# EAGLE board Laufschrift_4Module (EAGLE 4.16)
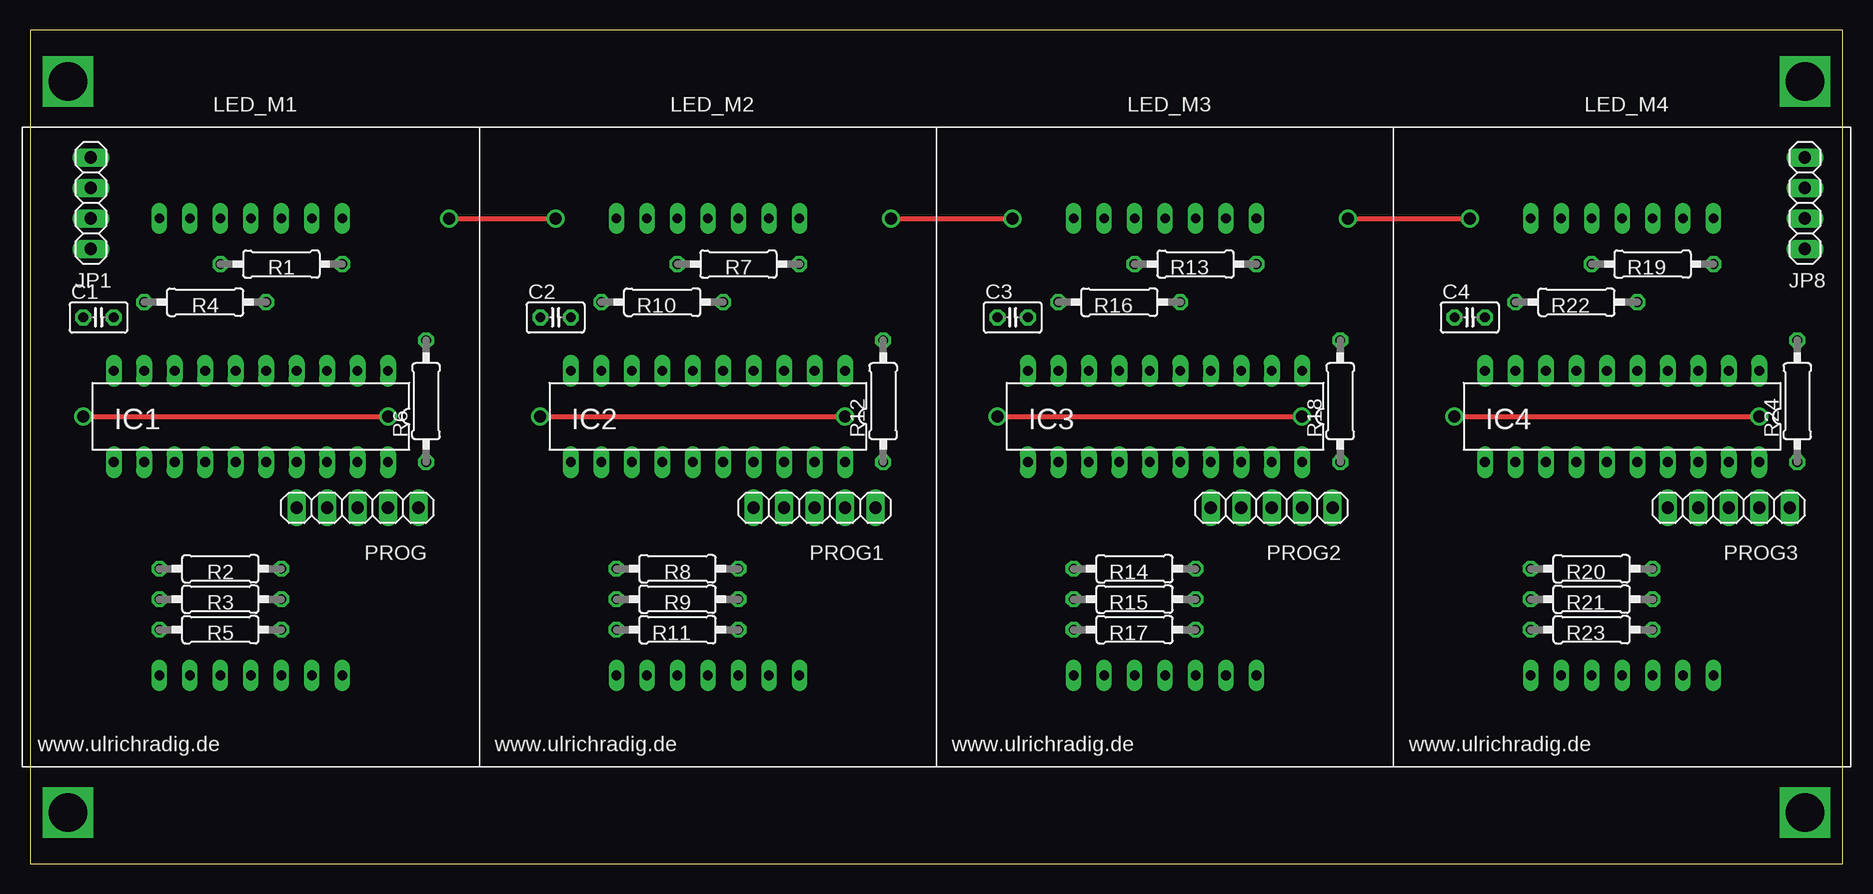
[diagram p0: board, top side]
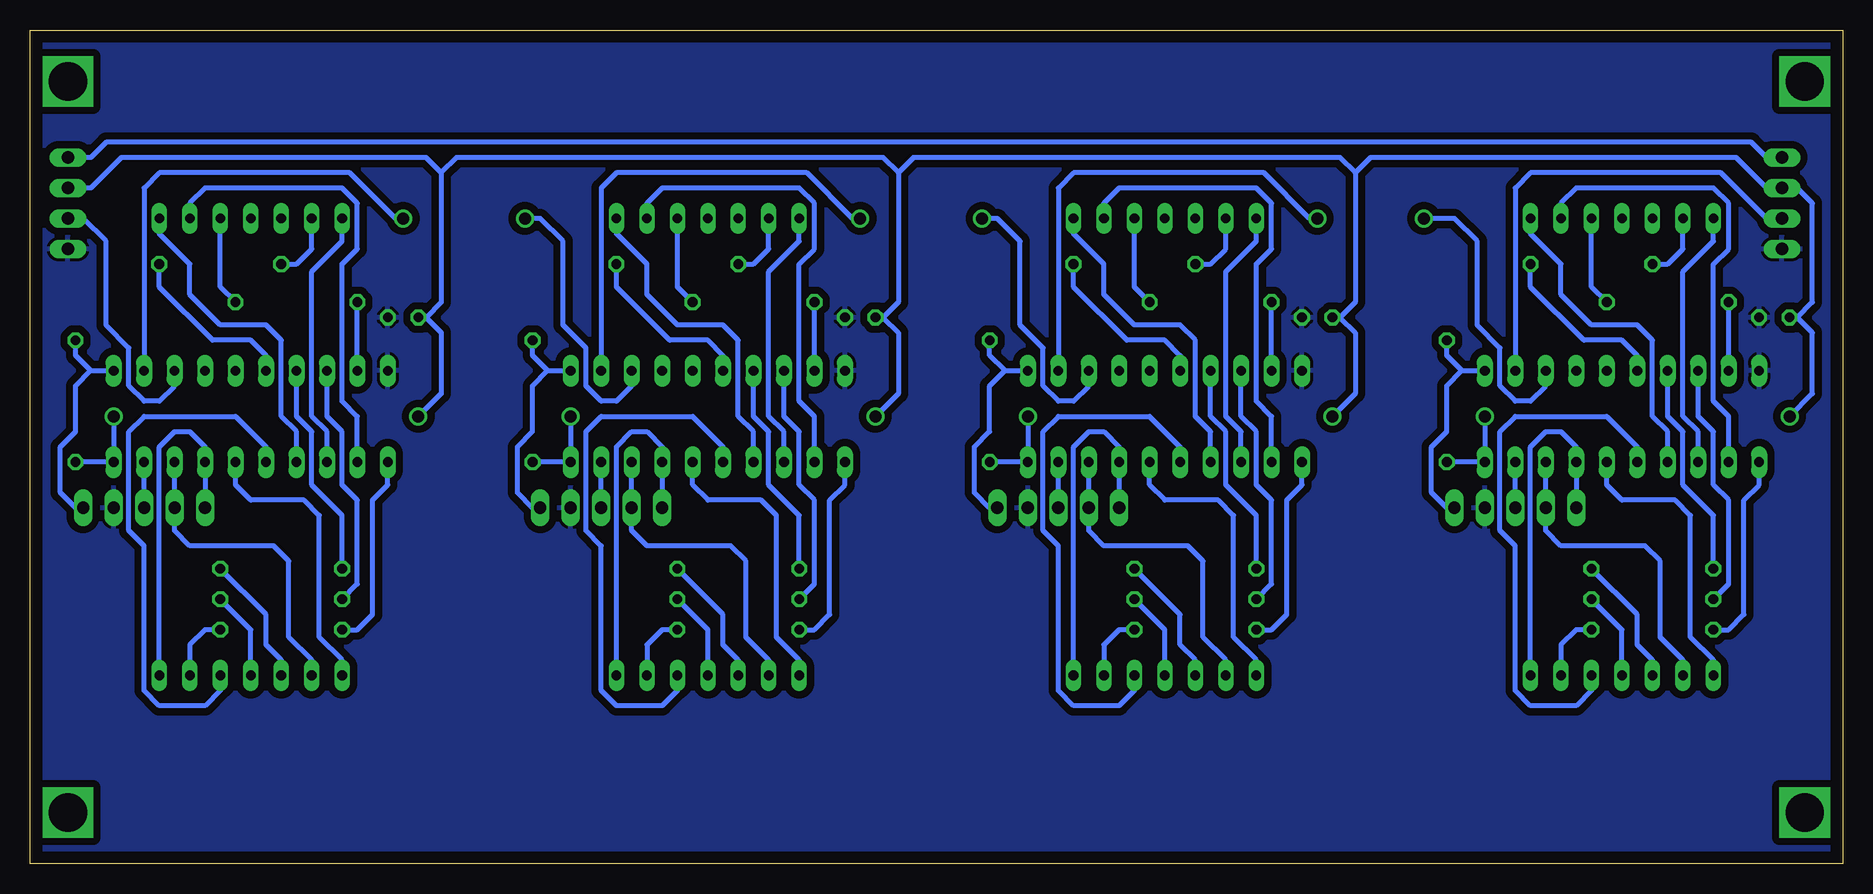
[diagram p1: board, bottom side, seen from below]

Size 151.11 x 69.52 mm. Coordinates in mm from the lower left corner, seen from the top.
Outline: 36.81,0 0,0 0,69.52 36.81,69.52
Outline: 36.83,0 151.11,0 151.11,69.52 36.83,69.52
Copper layers (1*16): Top 0.035mm / dielectric 1.5mm / Bottom 0.035mm
Design rules "default": minimum track width 10mil, minimum drill 24mil, track to track 8mil, track to pad 8mil, pad to pad 8mil, via to via 8mil, smd to smd 8mil, copper to edge 40mil, drill to drill 8mil, minimum pad ring 10mil, minimum via ring 8mil, stop-mask expansion 4mil, vias tented up to drill 0mil, thermal gap 10mil

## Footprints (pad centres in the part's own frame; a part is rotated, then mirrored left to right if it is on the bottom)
C025-025X050 = drill 0.813 octagon: 1 -1.27,0; 2 1.27,0
DIL20 = drill 0.813 long: 1 -11.43,-3.81; 2 -8.89,-3.81; 3 -6.35,-3.81; 4 -3.81,-3.81; 5 -1.27,-3.81; 6 1.27,-3.81; 7 3.81,-3.81; 8 6.35,-3.81; 9 8.89,-3.81; 10 11.43,-3.81; 11 11.43,3.81; 12 8.89,3.81; 13 6.35,3.81; 14 3.81,3.81; 15 1.27,3.81; 16 -1.27,3.81; 17 -3.81,3.81; 18 -6.35,3.81; 19 -8.89,3.81; 20 -11.43,3.81
1X04 = drill 1.016 long: 1 -3.81,0; 2 -1.27,0; 3 1.27,0; 4 3.81,0
LED_M = drill 0.8 long: 1 11.43,7.62; 2 13.97,7.62; 3 16.51,7.62; 4 19.05,7.62; 5 21.59,7.62; 6 24.13,7.62; 7 26.67,7.62; 8 26.67,45.72; 9 24.13,45.72; 10 21.59,45.72; 11 19.05,45.72; 12 16.51,45.72; 13 13.97,45.72; 14 11.43,45.72
1X05 = drill 1.016 long: 1 -5.08,0; 2 -2.54,0; 3 0,0; 4 2.54,0; 5 5.08,0
0207/10 = drill 0.813 octagon: 1 -5.08,0; 2 5.08,0

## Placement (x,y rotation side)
C1  [C025-025X050]  5.71,45.56 0 top
C2  [C025-025X050]  43.81,45.56 0 top
C3  [C025-025X050]  81.91,45.56 0 top
C4  [C025-025X050]  120.01,45.56 0 top
IC1  AT90S2313P  [DIL20]  18.41,37.3 180 top
IC2  AT90S2313P  [DIL20]  56.51,37.3 180 top
IC3  AT90S2313P  [DIL20]  94.61,37.3 180 top
IC4  AT90S2313P  [DIL20]  132.71,37.3 180 top
JP1  [1X04]  5.08,55.08 270 top
JP8  [1X04]  147.95,55.08 270 top
LED_M1  [LED_M]  -0.64,8.09 0 top
LED_M2  [LED_M]  37.46,8.09 0 top
LED_M3  [LED_M]  75.56,8.09 0 top
LED_M4  [LED_M]  113.66,8.09 0 top
PROG  [1X05]  27.3,29.68 180 top
PROG1  [1X05]  65.4,29.68 180 top
PROG2  [1X05]  103.5,29.68 180 top
PROG3  [1X05]  141.6,29.68 180 top
R1  [0207/10]  20.95,50 180 top
R2  [0207/10]  15.87,24.6 0 top
R3  [0207/10]  15.87,22.06 0 top
R4  [0207/10]  14.6,46.83 0 top
R5  [0207/10]  15.87,19.52 0 top
R6  [0207/10]  33.02,38.57 90 top
R7  [0207/10]  59.05,50 180 top
R8  [0207/10]  53.97,24.6 0 top
R9  [0207/10]  53.97,22.06 0 top
R10  [0207/10]  52.7,46.83 0 top
R11  [0207/10]  53.97,19.52 0 top
R12  [0207/10]  71.11,38.57 90 top
R13  [0207/10]  97.15,50 180 top
R14  [0207/10]  92.07,24.6 0 top
R15  [0207/10]  92.07,22.06 0 top
R16  [0207/10]  90.8,46.83 0 top
R17  [0207/10]  92.07,19.52 0 top
R18  [0207/10]  109.22,38.57 90 top
R19  [0207/10]  135.25,50 180 top
R20  [0207/10]  130.17,24.6 0 top
R21  [0207/10]  130.17,22.06 0 top
R22  [0207/10]  128.9,46.83 0 top
R23  [0207/10]  130.17,19.52 0 top
R24  [0207/10]  147.32,38.57 90 top

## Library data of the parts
C1-C4 R1-R24 = rcl
IC1-IC4 = atmel
JP1 JP8 PROG PROG1-PROG3 = pinhead
LED_M1-LED_M4 = led_matrix

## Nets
/RES: IC1.1 PROG.1 R6.2
/RES1: IC2.1 PROG1.1 R12.2
/RES2: IC3.1 PROG2.1 R18.2
/RES3: IC4.1 PROG3.1 R24.2
C1: LED_M1.13 R1.2
C2: LED_M1.3 R2.2
C3: LED_M1.4 R3.2
C4: LED_M1.10 R4.2
C5: LED_M1.6 R5.2
C6: LED_M2.6 R11.2
C7: LED_M2.10 R10.2
C8: LED_M2.4 R9.2
C9: LED_M2.3 R8.2
C10: LED_M2.13 R7.2
C11: LED_M3.6 R17.2
C12: LED_M3.10 R16.2
C13: LED_M3.4 R15.2
C14: LED_M3.3 R14.2
C15: LED_M3.13 R13.2
C16: LED_M4.6 R23.2
C17: LED_M4.10 R22.2
C18: LED_M4.4 R21.2
C19: LED_M4.3 R20.2
C20: LED_M4.13 R19.2
GND: C1.2 C2.2 C3.2 C4.2 IC1.10 IC2.10 IC3.10 IC4.10 JP1.4 JP8.4 PROG1.2 PROG2.2 PROG3.2 PROG.2
N$5: JP1.1 JP8.1
N$6: IC2.11 R11.1
N$7: IC2.9 R10.1
N$8: IC1.11 R5.1
N$9: IC1.9 R4.1
N$10: IC1.8 R3.1
N$11: IC1.7 R2.1
N$12: IC1.6 R1.1
N$13: IC2.8 R9.1
N$14: IC2.7 R8.1
N$15: IC2.6 R7.1
N$21: IC3.11 R17.1
N$22: IC3.9 R16.1
N$23: IC3.8 R15.1
N$24: IC3.7 R14.1
N$25: IC3.6 R13.1
N$31: IC4.11 R23.1
N$32: IC4.9 R22.1
N$33: IC4.8 R21.1
N$34: IC4.7 R20.1
N$35: IC4.6 R19.1
R1: IC1.12 LED_M1.9
R2: IC1.13 LED_M1.14
R3: IC1.14 LED_M1.8
R4: IC1.15 LED_M1.5
R5: IC1.16 LED_M1.1
R6: IC1.17 LED_M1.7 PROG.5
R7: IC1.18 LED_M1.2 PROG.4
R8: IC2.12 LED_M2.9
R9: IC2.13 LED_M2.14
R10: IC2.14 LED_M2.8
R11: IC2.15 LED_M2.5
R12: IC2.16 LED_M2.1
R13: IC2.17 LED_M2.7 PROG1.5
R14: IC2.18 LED_M2.2 PROG1.4
R15: IC3.12 LED_M3.9
R16: IC3.13 LED_M3.14
R17: IC3.14 LED_M3.8
R18: IC3.15 LED_M3.5
R19: IC3.16 LED_M3.1
R20: IC3.17 LED_M3.7 PROG2.5
R21: IC3.18 LED_M3.2 PROG2.4
R22: IC4.12 LED_M4.9
R23: IC4.13 LED_M4.14
R24: IC4.14 LED_M4.8
R25: IC4.15 LED_M4.5
R26: IC4.16 LED_M4.1
R27: IC4.17 LED_M4.7 PROG3.5
R28: IC4.18 LED_M4.2 PROG3.4
RXD: IC1.2 JP1.3
SCK: IC1.19 PROG.3
SCK1: IC2.19 PROG1.3
SCK2: IC3.19 PROG2.3
SCK3: IC4.19 PROG3.3
TXD: IC1.3 IC2.2
TXD1: IC2.3 IC3.2
TXD2: IC3.3 IC4.2
TXD3: IC4.3 JP8.3
VCC: C1.1 C2.1 C3.1 C4.1 IC1.20 IC2.20 IC3.20 IC4.20 JP1.2 JP8.2 R6.1 R12.1 R18.1 R24.1

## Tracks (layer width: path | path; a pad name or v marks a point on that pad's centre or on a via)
/RES
  Bottom 0.406: PROG.1 33.02,29.68 34.28,30.95 34.28,34.76 33.02,36.03 33.02,39.84 31.74,41.11 | 31.74,41.11 IC1.1 | R6.2 33.02,42.38 31.74,41.11
/RES1
  Bottom 0.406: PROG1.1 71.11,29.68 72.39,30.95 72.39,34.76 71.11,36.03 71.11,39.84 69.84,41.11 | 69.84,41.11 IC2.1 | R12.2 71.11,42.38 69.84,41.11
/RES2
  Bottom 0.406: PROG2.1 109.22,29.68 110.48,30.95 110.48,34.76 109.22,36.03 109.22,39.84 107.94,41.11 | 107.94,41.11 IC3.1 | R18.2 109.22,42.38 107.94,41.11
/RES3
  Bottom 0.406: PROG3.1 147.32,29.68 148.59,30.95 148.59,34.76 147.32,36.03 147.32,39.84 146.05,41.11 | 146.05,41.11 IC4.1 | R24.2 147.32,42.38 146.05,41.11
C1
  Bottom 0.406: R1.2 14.6,50 13.33,51.27 LED_M1.13
C2
  Bottom 0.406: LED_M1.3 15.87,16.98 17.14,18.25 17.14,20.79 R2.2
C3
  Bottom 0.406: LED_M1.4 18.41,19.52 R3.2
C4
  Bottom 0.406: R4.2 20.95,48.09 LED_M1.10
C5
  Bottom 0.406: R5.2 22.22,19.52 23.49,18.25 LED_M1.6
C6
  Bottom 0.406: R11.2 60.32,19.52 61.59,18.25 LED_M2.6
C7
  Bottom 0.406: R10.2 59.05,48.09 LED_M2.10
C8
  Bottom 0.406: LED_M2.4 56.51,19.52 R9.2
C9
  Bottom 0.406: LED_M2.3 53.97,16.98 55.24,18.25 55.24,20.79 R8.2
C10
  Bottom 0.406: R7.2 52.7,50 51.43,51.27 LED_M2.13
C11
  Bottom 0.406: R17.2 98.42,19.52 99.69,18.25 LED_M3.6
C12
  Bottom 0.406: R16.2 97.15,48.09 LED_M3.10
C13
  Bottom 0.406: LED_M3.4 94.61,19.52 R15.2
C14
  Bottom 0.406: LED_M3.3 92.07,16.98 93.34,18.25 93.34,20.79 R14.2
C15
  Bottom 0.406: R13.2 90.8,50 89.53,51.27 LED_M3.13
C16
  Bottom 0.406: R23.2 136.52,19.52 137.79,18.25 LED_M4.6
C17
  Bottom 0.406: R22.2 135.25,48.09 LED_M4.10
C18
  Bottom 0.406: LED_M4.4 132.71,19.52 R21.2
C19
  Bottom 0.406: LED_M4.3 130.17,16.98 131.44,18.25 131.44,20.79 R20.2
C20
  Bottom 0.406: R19.2 128.9,50 127.63,51.27 LED_M4.13
GND
  pour Bottom (isolate 0.61): -0.01,69.05 151.12,69.05 151.12,1.11 -0.01,1.11
N$1  (via drill 3.2)
  other vias: 3.17,65.24
N$3  (via drill 3.2)
  other vias: 3.17,4.28
N$5
  Bottom 0.406: JP1.1 6.35,58.89 7.62,60.16 144.78,60.16 146.05,58.89 JP8.1
N$6
  Bottom 0.406: R11.1 47.62,19.52 46.35,20.79 46.35,30.32 45.08,31.58 IC2.11
N$7
  Bottom 0.406: IC2.9 R10.1
N$8
  Bottom 0.406: R5.1 9.52,19.52 8.25,20.79 8.25,30.32 6.98,31.58 IC1.11
N$9
  Bottom 0.406: IC1.9 R4.1
N$10
  Bottom 0.406: R3.1 9.52,23.33 9.52,30.32 10.79,31.58 10.79,36.03 12.06,37.3 IC1.8
N$11
  Bottom 0.406: R2.1 10.79,29.04 13.33,31.58 13.33,36.03 14.6,37.3 IC1.7
N$12
  Bottom 0.406: IC1.6 17.14,42.38 18.41,43.65 21.59,43.65 26.03,48.09 R1.1
N$13
  Bottom 0.406: R9.1 47.62,23.33 47.62,30.32 48.89,31.58 48.89,36.03 50.16,37.3 IC2.8
N$14
  Bottom 0.406: R8.1 48.89,29.04 51.43,31.58 51.43,36.03 52.7,37.3 IC2.7
N$15
  Bottom 0.406: IC2.6 55.24,42.38 56.51,43.65 59.69,43.65 64.13,48.09 R7.1
N$21
  Bottom 0.406: R17.1 85.72,19.52 84.45,20.79 84.45,30.32 83.18,31.58 IC3.11
N$22
  Bottom 0.406: IC3.9 R16.1
N$23
  Bottom 0.406: R15.1 85.72,23.33 85.72,30.32 86.99,31.58 86.99,36.03 88.26,37.3 IC3.8
N$24
  Bottom 0.406: R14.1 86.99,29.04 89.53,31.58 89.53,36.03 90.8,37.3 IC3.7
N$25
  Bottom 0.406: IC3.6 93.34,42.38 94.61,43.65 97.78,43.65 102.23,48.09 R13.1
N$31
  Bottom 0.406: R23.1 123.82,19.52 122.55,20.79 122.55,30.32 121.28,31.58 IC4.11
N$32
  Bottom 0.406: IC4.9 R22.1
N$33
  Bottom 0.406: R21.1 123.82,23.33 123.82,30.32 125.09,31.58 125.09,36.03 126.36,37.3 IC4.8
N$34
  Bottom 0.406: R20.1 125.09,29.04 127.63,31.58 127.63,36.03 128.9,37.3 IC4.7
N$35
  Bottom 0.406: IC4.6 131.44,42.38 132.71,43.65 135.89,43.65 140.33,48.09 R19.1
N$37  (via drill 3.2)
  other vias: 147.95,65.24
N$39  (via drill 3.2)
  other vias: 147.95,4.28
R1
  Bottom 0.406: IC1.12 9.52,37.3 10.79,38.57 10.79,50 9.52,51.27 9.52,55.08 10.79,56.35 22.22,56.35 23.49,55.08 LED_M1.9
R2
  Bottom 0.406: IC1.13 12.06,36.03 13.33,37.3 13.33,49.37 10.79,51.91 LED_M1.14
R3
  Bottom 0.406: IC1.14 14.6,36.03 15.87,37.3 15.87,43.65 17.14,44.92 20.95,44.92 23.49,47.46 23.49,50 26.03,52.54 LED_M1.8
R4
  Bottom 0.406: IC1.15 17.14,34.76 19.68,37.3 27.3,37.3 28.57,36.03 28.57,27.78 27.3,26.5 27.3,14.44 26.03,13.17 22.22,13.17 20.95,14.44 LED_M1.5
R5
  Bottom 0.406: LED_M1.1 10.79,16.98 12.7,18.89 12.7,29.04 13.96,30.32 18.41,30.32 19.68,31.58 IC1.16
R6
  Bottom 0.406: LED_M1.7 26.03,34.76 24.76,36.03 23.49,36.03 22.22,34.76 IC1.17 PROG.5
R7
  Bottom 0.406: IC1.18 PROG.4 24.76,27.78 23.49,26.5 16.5,26.5 15.23,25.24 15.23,18.89 13.33,16.98 LED_M1.2
R8
  Bottom 0.406: IC2.12 47.62,37.3 48.89,38.57 48.89,50 47.62,51.27 47.62,55.08 48.89,56.35 60.32,56.35 61.59,55.08 LED_M2.9
R9
  Bottom 0.406: IC2.13 50.16,36.03 51.43,37.3 51.43,49.37 48.89,51.91 LED_M2.14
R10
  Bottom 0.406: IC2.14 52.7,36.03 53.97,37.3 53.97,43.65 55.24,44.92 59.05,44.92 61.59,47.46 61.59,50 64.13,52.54 LED_M2.8
R11
  Bottom 0.406: IC2.15 55.24,34.76 57.78,37.3 65.4,37.3 66.67,36.03 66.67,27.78 65.4,26.5 65.4,14.44 64.13,13.17 60.32,13.17 59.05,14.44 LED_M2.5
R12
  Bottom 0.406: LED_M2.1 48.89,16.98 50.8,18.89 50.8,29.04 52.06,30.32 56.51,30.32 57.78,31.58 IC2.16
R13
  Bottom 0.406: LED_M2.7 64.13,34.76 62.86,36.03 61.59,36.03 60.32,34.76 IC2.17 PROG1.5
R14
  Bottom 0.406: IC2.18 PROG1.4 62.86,27.78 61.59,26.5 54.6,26.5 53.34,25.24 53.34,18.89 51.43,16.98 LED_M2.2
R15
  Bottom 0.406: IC3.12 85.72,37.3 86.99,38.57 86.99,50 85.72,51.27 85.72,55.08 86.99,56.35 98.42,56.35 99.69,55.08 LED_M3.9
R16
  Bottom 0.406: IC3.13 88.26,36.03 89.53,37.3 89.53,49.37 86.99,51.91 LED_M3.14
R17
  Bottom 0.406: IC3.14 90.8,36.03 92.07,37.3 92.07,43.65 93.34,44.92 97.15,44.92 99.69,47.46 99.69,50 102.23,52.54 LED_M3.8
R18
  Bottom 0.406: IC3.15 93.34,34.76 95.88,37.3 103.5,37.3 104.77,36.03 104.77,27.78 103.5,26.5 103.5,14.44 102.23,13.17 98.42,13.17 97.15,14.44 LED_M3.5
R19
  Bottom 0.406: LED_M3.1 86.99,16.98 88.89,18.89 88.89,29.04 90.17,30.32 94.61,30.32 95.88,31.58 IC3.16
R20
  Bottom 0.406: LED_M3.7 102.23,34.76 100.96,36.03 99.69,36.03 98.42,34.76 IC3.17 PROG2.5
R21
  Bottom 0.406: IC3.18 PROG2.4 100.96,27.78 99.69,26.5 92.7,26.5 91.44,25.24 91.44,18.89 89.53,16.98 LED_M3.2
R22
  Bottom 0.406: IC4.12 123.82,37.3 125.09,38.57 125.09,50 123.82,51.27 123.82,55.08 125.09,56.35 136.52,56.35 137.79,55.08 LED_M4.9
R23
  Bottom 0.406: IC4.13 126.36,36.03 127.63,37.3 127.63,49.37 125.09,51.91 LED_M4.14
R24
  Bottom 0.406: IC4.14 128.9,36.03 130.17,37.3 130.17,43.65 131.44,44.92 135.25,44.92 137.79,47.46 137.79,50 140.33,52.54 LED_M4.8
R25
  Bottom 0.406: IC4.15 131.44,34.76 133.98,37.3 141.6,37.3 142.87,36.03 142.87,27.78 141.6,26.5 141.6,14.44 140.33,13.17 136.52,13.17 135.25,14.44 LED_M4.5
R26
  Bottom 0.406: LED_M4.1 125.09,16.98 127,18.89 127,29.04 128.27,30.32 132.71,30.32 133.98,31.58 IC4.16
R27
  Bottom 0.406: LED_M4.7 140.33,34.76 139.06,36.03 137.79,36.03 136.52,34.76 IC4.17 PROG3.5
R28
  Bottom 0.406: IC4.18 PROG3.4 139.06,27.78 137.79,26.5 130.81,26.5 129.54,25.24 129.54,18.89 127.63,16.98 LED_M4.2
RXD
  Bottom 0.406: JP1.3 6.35,53.81 10.15,57.62 26.03,57.62 27.3,56.35 IC1.2
SCK
  Bottom 0.406: PROG.3 IC1.19
SCK1
  Bottom 0.406: PROG1.3 IC2.19
SCK2
  Bottom 0.406: PROG2.3 IC3.19
SCK3
  Bottom 0.406: PROG3.3 IC4.19
TXD  (via drill 1)
  Top 0.406: v34.92,53.81 v43.81,53.81
  Bottom 0.406: v43.81,53.81 44.45,53.81 48.26,57.62 64.13,57.62 65.4,56.35 IC2.2 | IC1.3 24.76,39.84 26.03,38.57 27.3,38.57 28.57,39.84 28.57,43.02 30.47,44.92 30.47,51.91 32.38,53.81 v34.92,53.81
TXD1  (via drill 1)
  Top 0.406: v71.75,53.81 v81.91,53.81
  Bottom 0.406: IC2.3 62.86,39.84 64.13,38.57 65.4,38.57 66.67,39.84 66.67,43.02 68.58,44.92 68.58,51.91 70.48,53.81 v71.75,53.81 | v81.91,53.81 82.55,53.81 86.36,57.62 102.23,57.62 103.5,56.35 IC3.2
TXD2  (via drill 1)
  Top 0.406: v109.85,53.81 v120.01,53.81
  Bottom 0.406: IC3.3 100.96,39.84 102.23,38.57 103.5,38.57 104.77,39.84 104.77,43.02 106.67,44.92 106.67,51.91 108.58,53.81 v109.85,53.81 | v120.01,53.81 120.64,53.81 124.45,57.62 140.33,57.62 141.6,56.35 IC4.2
TXD3
  Bottom 0.406: IC4.3 139.06,39.84 140.33,38.57 141.6,38.57 142.87,39.84 142.87,43.02 144.78,44.92 144.78,51.91 146.68,53.81 JP8.3
VCC  (via drill 1)
  Top 0.406: v4.44,37.3 v29.84,37.3 v4.44,37.3 | v42.54,37.3 v67.94,37.3 v42.54,37.3 | v80.64,37.3 v106.04,37.3 v80.64,37.3 | v118.74,37.3 v144.14,37.3 v118.74,37.3
  Bottom 0.406: v29.84,37.3 IC1.20 R6.1 | v4.44,37.3 2.53,39.2 2.53,44.28 3.81,45.56 | 3.81,45.56 C1.1 | 3.81,45.56 2.53,46.83 2.53,55.08 3.81,56.35 JP1.2 6.35,56.35 8.88,58.89 39.37,58.89 40.63,57.62 | v67.94,37.3 IC2.20 R12.1 | v42.54,37.3 40.63,39.2 40.63,44.28 41.91,45.56 | 40.63,57.62 41.91,58.89 77.47,58.89 78.73,57.62 | 41.91,45.56 C2.1 | 40.63,57.62 40.63,46.83 41.91,45.56 | v106.04,37.3 IC3.20 R18.1 | v80.64,37.3 78.73,39.2 78.73,44.28 80,45.56 | 78.73,57.62 80,58.89 115.56,58.89 116.83,57.62 | 80,45.56 C3.1 | 78.73,57.62 78.73,46.83 80,45.56 | 146.05,56.35 143.51,58.89 118.11,58.89 116.83,57.62 | 146.05,56.35 JP8.2 | 146.05,56.35 149.22,56.35 | v144.14,37.3 IC4.20 R24.1 | v118.74,37.3 116.83,39.2 116.83,44.28 118.11,45.56 | 118.11,45.56 C4.1 | 116.83,57.62 116.83,46.83 118.11,45.56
